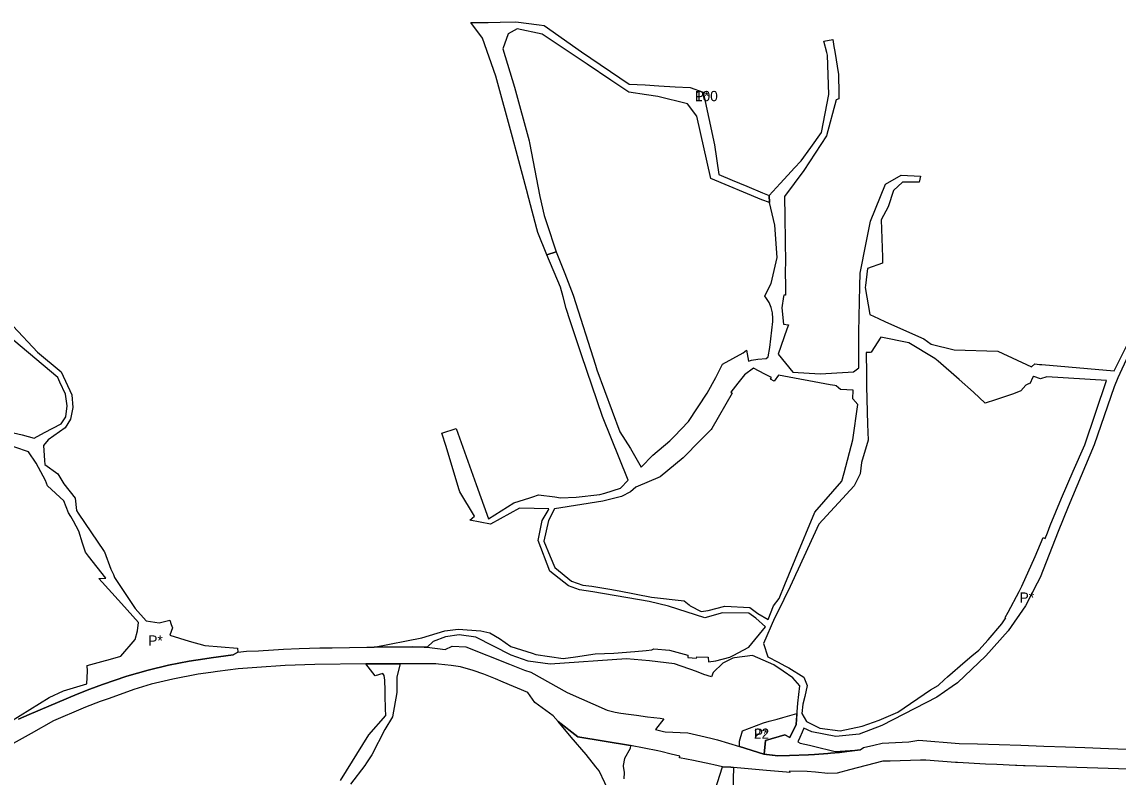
# Model space of a CAD drawing. Extents: x -501732 to -497665, y -1142022 to -1138283.
# Drawn here: x -498822 to -498074, y -1140337 to -1139823 of the extents above; entities that cross this region are included whole.
import ezdxf

# ---------------------------------------------------------------- set-up
doc = ezdxf.new("R2010")
doc.units = 0
for name, color, linetype in [('4', 7, 'Continuous'), ('43', 7, 'Continuous'), ('44', 7, 'Continuous'), ('61', 7, 'Continuous')]:
    doc.layers.add(name, color=color, linetype=linetype)

msp = doc.modelspace()

# ---------------------------------------------------------------- linework, layer by layer
at = {"layer": '4'}
for points in [[(-498823.821, -1140297.619), (-498816.65, -1140294.45), (-498783.82, -1140280.61), (-498775.13, -1140277.11), (-498766.57, -1140274.02), (-498749.99, -1140268.32), (-498735.38, -1140264.17), (-498721.62, -1140260.84), (-498707.43, -1140258.11), (-498696.917, -1140256.467), (-498692.52, -1140255.78), (-498677.54, -1140253.8), (-498674.42, -1140251.94), (-498668.5, -1140251.32), (-498660.19, -1140250.97), (-498656.98, -1140250.84), (-498653.516, -1140250.617), (-498643.16, -1140249.95), (-498632.42, -1140249.56), (-498618.48, -1140249.06), (-498610.11, -1140248.97), (-498586.32, -1140248.64), (-498581.41, -1140248.56), (-498555.48, -1140248.23), (-498547.23, -1140248.6), (-498545.22, -1140248.67), (-498533.03, -1140250.13), (-498528.28, -1140247.99), (-498518.98, -1140248.4), (-498489.252, -1140260.061), (-498478.83, -1140264.15), (-498474.55, -1140265.61), (-498449.81, -1140279.55), (-498422.46, -1140291.59), (-498417.02, -1140292.85), (-498413.36, -1140293.41), (-498407.93, -1140294.24), (-498402.54, -1140294.98), (-498395.12, -1140296.01), (-498386.45, -1140297.04), (-498383.84, -1140297.37), (-498389.51, -1140304.68), (-498384.14, -1140306), (-498382.92, -1140306.3), (-498367.49, -1140306.95), (-498358.69, -1140308.93), (-498351.926, -1140310.544), (-498347.46, -1140311.61), (-498332.46, -1140316.29), (-498315.69, -1140321.52), (-498306.23, -1140322.62), (-498298.17, -1140322.38), (-498285.32, -1140322.01), (-498281.18, -1140321.68), (-498272.152, -1140320.952), (-498270.39, -1140320.81), (-498264.24, -1140320.32), (-498259.25, -1140319.74), (-498250.06, -1140318.42), (-498247.78, -1140316.98), (-498240.77, -1140315.36), (-498235.15, -1140314.06), (-498217.04, -1140313), (-498210.03, -1140312.01), (-498182.55, -1140314.14), (-498170.07, -1140314.45), (-498140.47, -1140315.37), (-498124.82, -1140315.96), (-498110.03, -1140316.5), (-498097.04, -1140316.97), (-498080.83, -1140317.66), (-498061.89, -1140318.32)], [(-498067.02, -1140331.73), (-498116.41, -1140330.16), (-498122.63, -1140329.92), (-498137.66, -1140329.36), (-498138.72, -1140329.34), (-498143.34, -1140329.15), (-498144.23, -1140329.16), (-498156.92, -1140328.57), (-498164.72, -1140328.21), (-498183.68, -1140327.23), (-498185.141, -1140327.124), (-498205.41, -1140325.65), (-498209.03, -1140325.65), (-498229.56, -1140326.13), (-498234.59, -1140326.25), (-498257.27, -1140332.11), (-498265.69, -1140334.29), (-498272.19, -1140334.73), (-498280.63, -1140333.62), (-498286.3, -1140333.18), (-498298.2, -1140332.93), (-498298.11, -1140333.99), (-498300.34, -1140333.79), (-498313.9, -1140332.58), (-498336.48, -1140330.57), (-498338.22, -1140330.42), (-498343.94, -1140330.1), (-498349.77, -1140328.7), (-498352.01, -1140328.16), (-498363.71, -1140325.78), (-498373.23, -1140323.93), (-498373.06, -1140322.8), (-498378.87, -1140321.407), (-498385.91, -1140319.72), (-498388.12, -1140319.18), (-498406.57, -1140315.55), (-498442.63, -1140309.69), (-498456.08, -1140299.18), (-498459.41, -1140295.23), (-498471.93, -1140286.24), (-498476.75, -1140279.49), (-498493.47, -1140272.31), (-498498.65, -1140270.21), (-498506.59, -1140267), (-498513.82, -1140264.42), (-498522.53, -1140261.93), (-498528.97, -1140260.98), (-498537.52, -1140260.05), (-498539.34, -1140259.87), (-498563.73, -1140259.82), (-498569.6, -1140259.82), (-498579.22, -1140259.84), (-498587.11, -1140259.99), (-498621.81, -1140260.32), (-498641.97, -1140261.14), (-498661.41, -1140262.33), (-498674.17, -1140263.33), (-498688.25, -1140265.21), (-498692.64, -1140265.8), (-498701.35, -1140267.06), (-498718.64, -1140270.31), (-498733.5, -1140273.81), (-498745.17, -1140277.37), (-498762.153, -1140283.475), (-498768.23, -1140285.66), (-498778.09, -1140289.42), (-498779.71, -1140290.04), (-498799.88, -1140298.7), (-498815.24, -1140307.37), (-498831.5, -1140316.35)]]:
    msp.add_lwpolyline(points, dxfattribs=at)
at = {"layer": '43'}
for points in [[(-498061.7, -1140037.59), (-498074.46, -1140064.99), (-498076.9, -1140071.11), (-498090.56, -1140110.67), (-498108.39, -1140152.98), (-498115.098, -1140169.861), (-498127.49, -1140201.05), (-498129.511, -1140204.996), (-498137.41, -1140220.42), (-498149.3, -1140237.45), (-498164.48, -1140254.47), (-498183.78, -1140272.87), (-498187.37, -1140275.36), (-498197.77, -1140282.61), (-498235.28, -1140301.81), (-498250.87, -1140307.86), (-498266.58, -1140309.38), (-498283.1, -1140306.27), (-498288.43, -1140303.7), (-498289.64, -1140306.45), (-498291.29, -1140310.21), (-498292.56, -1140313.09), (-498291.06, -1140313.88), (-498284.66, -1140315.3), (-498275.58, -1140317.5), (-498273.4, -1140318.03), (-498267.08, -1140319.56), (-498250.06, -1140318.42), (-498259.25, -1140319.74), (-498264.24, -1140320.32), (-498270.39, -1140320.81), (-498272.152, -1140320.952), (-498281.18, -1140321.68), (-498285.32, -1140322.01), (-498298.17, -1140322.38), (-498306.23, -1140322.62), (-498315.607, -1140321.53), (-498315.491, -1140321.347), (-498314.594, -1140312.178), (-498301.442, -1140308.177), (-498297.97, -1140310.07), (-498296.847, -1140307.688), (-498294.94, -1140303.65), (-498293.75, -1140301.13), (-498292.7, -1140286.76), (-498291.25, -1140274.91), (-498296.02, -1140269.52), (-498302.59, -1140265.01), (-498309.07, -1140260.58), (-498323.5, -1140254.23), (-498335.704, -1140255.871), (-498336.89, -1140256.03), (-498343.63, -1140259.45), (-498350.3, -1140265.88), (-498351.49, -1140268.8), (-498356.78, -1140267.13), (-498361.68, -1140265.12), (-498376.71, -1140259.93), (-498393.76, -1140257.98), (-498409.49, -1140256.52), (-498461.5, -1140260.09), (-498476.48, -1140258.14), (-498488.09, -1140253.97), (-498512.04, -1140241.67), (-498523.57, -1140240.06), (-498532.76, -1140241.54), (-498541.15, -1140244.61), (-498545.22, -1140248.67), (-498547.23, -1140248.6), (-498555.48, -1140248.23), (-498581.41, -1140248.56), (-498548.92, -1140242.09), (-498533.15, -1140237.41), (-498524.03, -1140236.23), (-498508.76, -1140237.36), (-498502.5, -1140238.77), (-498496.04, -1140242.6), (-498488.21, -1140248.03), (-498473.63, -1140252.73), (-498471.13, -1140253.54), (-498452.47, -1140256.2), (-498444.26, -1140255.2), (-498430.79, -1140253.04), (-498418.03, -1140252.63), (-498403.7, -1140251.43), (-498395.92, -1140250.75), (-498392.08, -1140250.42), (-498390.87, -1140249.7), (-498380.09, -1140250.61), (-498367.51, -1140253.98), (-498367.62, -1140255.67), (-498361.58, -1140256.05), (-498361.52, -1140255.12), (-498353.82, -1140255.42), (-498353.58, -1140258.58), (-498348.41, -1140257.97), (-498338.9, -1140255.42), (-498336.718, -1140254.246), (-498325.98, -1140248.47), (-498314.71, -1140234.62), (-498321.12, -1140228.78), (-498326.08, -1140225.5), (-498343.96, -1140225.17), (-498356.086, -1140228.474), (-498380.78, -1140220.65), (-498393.84, -1140217.41), (-498432.34, -1140210.8), (-498441.49, -1140209.43), (-498449.01, -1140206.85), (-498461.59, -1140196.84), (-498469.59, -1140175.97), (-498466.93, -1140162.26), (-498462.85, -1140155.45), (-498462.372, -1140154.316), (-498482.3, -1140153.95), (-498502.12, -1140164.77), (-498516.23, -1140162.11), (-498513.07, -1140159.27), (-498523.05, -1140142.79), (-498523.662, -1140140.759), (-498532.36, -1140111.9), (-498535.385, -1140102.658), (-498525.46, -1140099.67), (-498511.813, -1140137.832), (-498503.51, -1140161.05), (-498486.14, -1140150.27), (-498475.38, -1140146.76), (-498473.2, -1140146.05), (-498469.37, -1140144.8), (-498458.25, -1140146.09), (-498454.39, -1140146.74), (-498443.79, -1140146.41), (-498427.49, -1140144.66), (-498424.15, -1140143.6), (-498413.47, -1140140.15), (-498408.36, -1140134.77), (-498425.83, -1140091.5), (-498440.06, -1140049.48), (-498447.8, -1140026.22), (-498450.51, -1140017.8), (-498452.658, -1140009.919), (-498454.43, -1140003.42), (-498463.633, -1139981.263), (-498457.33, -1139979.14), (-498451.44, -1139994.1), (-498445.81, -1140008.75), (-498430.63, -1140056.46), (-498429.55, -1140059.73), (-498414.01, -1140101.85), (-498406.6, -1140113.23), (-498399.47, -1140125.86), (-498391.35, -1140117.72), (-498379.94, -1140107.93), (-498376.98, -1140104.93), (-498367.04, -1140094.89), (-498354.41, -1140075.56), (-498348.44, -1140064.85), (-498343.92, -1140055.76), (-498329.9, -1140048.05), (-498327.63, -1140046.16), (-498326.21, -1140053.73), (-498324.14, -1140053.08), (-498319.865, -1140052.462), (-498314.21, -1140051.96), (-498312.82, -1140050.68), (-498311.73, -1140044.52), (-498309.61, -1140026.78), (-498309.55, -1140024.6), (-498309.95, -1140020.8), (-498310.85, -1140017.19), (-498312.14, -1140013.66), (-498314.33, -1140010.4), (-498315.09, -1140009.49), (-498314.561, -1140008.389), (-498310.87, -1140000.71), (-498306.6, -1139983.05), (-498308.38, -1139960.97), (-498312.02, -1139945.53), (-498312.25, -1139940.81), (-498304.74, -1139932.72), (-498296.9, -1139924.27), (-498295.019, -1139922.247), (-498290.42, -1139917.3), (-498283.8, -1139908.18), (-498276.41, -1139898), (-498271.57, -1139872.1), (-498272.28, -1139845.36), (-498272.76, -1139843.53), (-498274.81, -1139835.71), (-498268.747, -1139834.697), (-498267.99, -1139839.29), (-498267.45, -1139842.69), (-498264.86, -1139858.44), (-498264.7, -1139871.4), (-498264.68, -1139875), (-498266.38, -1139875.75), (-498273.16, -1139900.19), (-498288.6, -1139923.77), (-498301.64, -1139941.55), (-498301.42, -1139955.34), (-498301.23, -1139971.84), (-498301.06, -1139986.7), (-498301.24, -1139991.74), (-498301.17, -1139995.25), (-498301.03, -1140000.2), (-498300.93, -1140007.983), (-498300.92, -1140008.75), (-498302.19, -1140008.78), (-498302.348, -1140009.778), (-498303.54, -1140017.31), (-498302.35, -1140028.57), (-498299.07, -1140028.89), (-498300.13, -1140032.02), (-498305.9, -1140049.01), (-498295.98, -1140061.11), (-498277.4, -1140062.39), (-498258.207, -1140061.144), (-498254.75, -1140060.92), (-498251.1, -1140058.34), (-498251.1, -1140034.03), (-498250.281, -1140002.595), (-498250.05, -1139993.72), (-498245.93, -1139973.13), (-498243, -1139958.38), (-498232.94, -1139933.15), (-498222.1, -1139927.02), (-498208.976, -1139927.588), (-498209.97, -1139931.8), (-498221.15, -1139931.74), (-498227.48, -1139937.56), (-498230.99, -1139948.51), (-498235.68, -1139957.35), (-498234.9, -1139982.88), (-498234.8, -1139986.89), (-498245.04, -1139990.65), (-498246.528, -1140002.195), (-498246.71, -1140003.61), (-498243.41, -1140021.97), (-498237.54, -1140024.75), (-498232.76, -1140027.01), (-498206.6, -1140038.42), (-498201.77, -1140042.24), (-498186.06, -1140046.03), (-498156.37, -1140046.94), (-498133.22, -1140057.57), (-498131.04, -1140055.59), (-498127.83, -1140055.88), (-498126.38, -1140056.01), (-498076.93, -1140060.36), (-498067.12, -1140040.83)], [(-498827.53, -1140029.8), (-498810.94, -1140047.51), (-498794.68, -1140061.09), (-498787.4, -1140076.72), (-498786.81, -1140085.38), (-498788.4, -1140093.31), (-498791.97, -1140099.03), (-498803.72, -1140107.33), (-498806.72, -1140111.26), (-498806.12, -1140121.34), (-498805.96, -1140124.04), (-498797.06, -1140130.39), (-498792.94, -1140137.4), (-498785.13, -1140146.99), (-498784.33, -1140155.47), (-498783.09, -1140157.29), (-498765.341, -1140183.345), (-498765.14, -1140183.64), (-498760.93, -1140195.45), (-498759.13, -1140198.99), (-498758.32, -1140201.06), (-498744.33, -1140222.22), (-498736.74, -1140230.62), (-498728.02, -1140231.9), (-498720.61, -1140230.13), (-498719.68, -1140233.04), (-498718.91, -1140235.42), (-498720.75, -1140240.46), (-498707.55, -1140244.38), (-498696.93, -1140247.39), (-498674.61, -1140249.31), (-498674.42, -1140251.94), (-498677.54, -1140253.8), (-498692.52, -1140255.78), (-498696.917, -1140256.467), (-498707.43, -1140258.11), (-498721.62, -1140260.84), (-498735.38, -1140264.17), (-498749.99, -1140268.32), (-498766.57, -1140274.02), (-498775.13, -1140277.11), (-498783.82, -1140280.61), (-498816.65, -1140294.45), (-498823.821, -1140297.619)], [(-498830.17, -1140101.82), (-498821.4, -1140104), (-498813.28, -1140106.07), (-498806.03, -1140102.32), (-498794.69, -1140096.4), (-498791.67, -1140091.74), (-498790.59, -1140084.24), (-498791.81, -1140076.15), (-498795.59, -1140067.95), (-498797.14, -1140064.74), (-498827.06, -1140039.73)], [(-498829.21, -1140299.26), (-498803.03, -1140282.74), (-498793.26, -1140278.25), (-498777.38, -1140273.51), (-498776.85, -1140264.93), (-498777.08, -1140261.08), (-498767.03, -1140258.26), (-498761.23, -1140256.7), (-498753.99, -1140254.6), (-498744.4, -1140243.24), (-498742.7, -1140237.5), (-498742.1, -1140231.69), (-498753.68, -1140218.75), (-498769.17, -1140201.83), (-498764.41, -1140201.57), (-498776.207, -1140186.494), (-498778.26, -1140183.87), (-498780.168, -1140177.757), (-498782.76, -1140169.45), (-498786.46, -1140162.69), (-498788.14, -1140159.61), (-498789.78, -1140157.06), (-498793.05, -1140148.95), (-498804.13, -1140138.54), (-498805.36, -1140135.08), (-498811.79, -1140123.29), (-498816.96, -1140115.59), (-498835.67, -1140109.02)], [(-498604.38, -1140339.37), (-498585.04, -1140308.39), (-498573.54, -1140295.16), (-498573.63, -1140290.61), (-498573.83, -1140281.41), (-498573.926, -1140277.036), (-498574.03, -1140272.26), (-498574.2, -1140270.99), (-498574.64, -1140267.8), (-498575.38, -1140266.51), (-498580.72, -1140267.98), (-498587.11, -1140259.99), (-498579.22, -1140259.84), (-498569.6, -1140259.82), (-498563.73, -1140259.82), (-498565.96, -1140268.7), (-498565.894, -1140279.424), (-498568.811, -1140295.953), (-498574.07, -1140304.58), (-498582.98, -1140321.99), (-498586.54, -1140327.36), (-498587.81, -1140329.06), (-498597.43, -1140341.87)], [(-498420.41, -1140349.26), (-498428.12, -1140332.76), (-498430.19, -1140330.18), (-498436.98, -1140321.7), (-498447.13, -1140309.8), (-498448.03, -1140308.73), (-498452.83, -1140303.04), (-498456.08, -1140299.18), (-498442.63, -1140309.69), (-498406.57, -1140315.55), (-498406.88, -1140317.48), (-498410.76, -1140324.38), (-498411.65, -1140329.22), (-498411.59, -1140329.65), (-498410.95, -1140334.03), (-498411.23, -1140338.15)], [(-498350.67, -1140351.45), (-498343.94, -1140330.1), (-498338.22, -1140330.42), (-498336.48, -1140330.57), (-498337.19, -1140354.3)]]:
    msp.add_lwpolyline(points, dxfattribs=at)
for points in [[(-498245.813, -1140062.69), (-498245.72, -1140069), (-498245.695, -1140070.649), (-498245.56, -1140079.69), (-498245.01, -1140096.73), (-498244.66, -1140107.6), (-498249.22, -1140122.8), (-498250.18, -1140130.39), (-498253.29, -1140136.79), (-498254.17, -1140138.59), (-498278.21, -1140164.82), (-498292.45, -1140195.38), (-498294.19, -1140199.34), (-498295.14, -1140201.33), (-498297.91, -1140207.14), (-498306.37, -1140224.92), (-498308.39, -1140228.91), (-498315.93, -1140246.15), (-498313, -1140255.19), (-498306.02, -1140258.81), (-498301.39, -1140261.22), (-498298.65, -1140262.64), (-498288.552, -1140268.889), (-498286.22, -1140274.76), (-498287.91, -1140282.14), (-498289.28, -1140287.42), (-498289.8, -1140293.86), (-498286.8, -1140299.31), (-498277.5, -1140303.8), (-498263.78, -1140305.62), (-498248.72, -1140302.38), (-498237.09, -1140298.36), (-498224.54, -1140292.78), (-498202.1, -1140277.73), (-498196.9, -1140274.61), (-498192.56, -1140270.63), (-498190.56, -1140268.87), (-498178.51, -1140258.27), (-498174.04, -1140254.5), (-498169.27, -1140250.49), (-498162.87, -1140243.45), (-498153.62, -1140232.76), (-498150.82, -1140228.58), (-498151.17, -1140228.44), (-498149.24, -1140224.81), (-498141.66, -1140210.54), (-498140, -1140206.89), (-498130.83, -1140186.73), (-498125.43, -1140173.84), (-498124.04, -1140174.42), (-498122.51, -1140170.7), (-498120.485, -1140165.769), (-498112.8, -1140147.05), (-498104.9, -1140128.69), (-498096.88, -1140110.66), (-498082.17, -1140066.94), (-498122.79, -1140064.35), (-498127.17, -1140065.71), (-498131.65, -1140064.06), (-498132.33, -1140064.71), (-498134.37, -1140069.22), (-498134.83, -1140069.03), (-498137.2, -1140070.01), (-498140.47, -1140073.95), (-498145.53, -1140075.99), (-498157.95, -1140080.06), (-498164.8, -1140082.31), (-498172.81, -1140074.74), (-498182.72, -1140066.17), (-498197.01, -1140053.8), (-498199.22, -1140051.89), (-498217.04, -1140041.19), (-498235.96, -1140037.35), (-498242.66, -1140047.68), (-498243.31, -1140047.71), (-498246.03, -1140047.86)], [(-498370.82, -1140119.62), (-498386.48, -1140132.43), (-498403.14, -1140139.56), (-498406.6, -1140142.83), (-498412.76, -1140145.86), (-498425.44, -1140149.16), (-498458.36, -1140154.39), (-498462.65, -1140162.35), (-498465.69, -1140176.33), (-498461.4, -1140186.69), (-498458.23, -1140194.36), (-498446.94, -1140203.64), (-498439.06, -1140206.23), (-498433.02, -1140206.9), (-498420.67, -1140209.11), (-498414.42, -1140210.23), (-498392.34, -1140214.39), (-498370.01, -1140216.96), (-498366.666, -1140219.765), (-498366.04, -1140220.29), (-498358.48, -1140224.17), (-498353.64, -1140223.54), (-498342.31, -1140220.68), (-498325.42, -1140221.54), (-498319.92, -1140225.51), (-498312.75, -1140229.64), (-498309.12, -1140220.4), (-498305.28, -1140215.33), (-498301.36, -1140205.83), (-498294.38, -1140188.9), (-498281.07, -1140156.62), (-498262.53, -1140135.39), (-498261.081, -1140129.835), (-498255.2, -1140107.29), (-498251.7, -1140083.22), (-498255.09, -1140079.42), (-498254.77, -1140073.58), (-498263.6, -1140073.1), (-498264.88, -1140071.91), (-498266.48, -1140070.42), (-498267.31, -1140070.3), (-498270.56, -1140069.78), (-498305.74, -1140063.26), (-498308.63, -1140067.26), (-498311.13, -1140065.93), (-498310.61, -1140064.89), (-498315.04, -1140062.61), (-498322.89, -1140058.57), (-498329.04, -1140062.94), (-498333.43, -1140068.6), (-498338.3, -1140074.88), (-498337.34, -1140075.59), (-498351.314, -1140099.493), (-498351.71, -1140100.17), (-498358.95, -1140107.54)]]:
    msp.add_lwpolyline(points, close=True, dxfattribs=at)
at = {"layer": '44'}
for points in [[(-498465.57, -1139825.05), (-498440.12, -1139843.07), (-498407.57, -1139864.95), (-498396.76, -1139865.58), (-498387.46, -1139866.13), (-498376.13, -1139866.79), (-498366.03, -1139867.38), (-498357.08, -1139870.37), (-498349.49, -1139906.31), (-498346.55, -1139926.58), (-498337.43, -1139930.36), (-498327.27, -1139934.57), (-498316.68, -1139938.97), (-498312.25, -1139940.81), (-498312.02, -1139945.53), (-498317.03, -1139943.71), (-498351.84, -1139929.26), (-498361.41, -1139886.77), (-498367.74, -1139878.37), (-498387.92, -1139873.33), (-498395.68, -1139872.23), (-498407.82, -1139870.52), (-498420.17, -1139862.22), (-498436.13, -1139851.5), (-498466.78, -1139830.91), (-498483.91, -1139827.39), (-498490.11, -1139830.78), (-498493.62, -1139840.95), (-498485.75, -1139867.1), (-498475.72, -1139903.67), (-498475.454, -1139905.076), (-498468.54, -1139941.63), (-498465.55, -1139954.43), (-498463.929, -1139959.303), (-498457.33, -1139979.14), (-498463.633, -1139981.263), (-498469.91, -1139966.15), (-498470.57, -1139963.59), (-498475.92, -1139942.9), (-498477.58, -1139936.75), (-498483.736, -1139913.929), (-498487.19, -1139901.13), (-498498.38, -1139859.65), (-498507.55, -1139833.78), (-498515.401, -1139823.08), (-498503.66, -1139822.92), (-498495.48, -1139822.79), (-498484.9, -1139822.62), (-498469.03, -1139824.62)], [(-498296.847, -1140307.688), (-498297.97, -1140310.07), (-498301.442, -1140308.177), (-498314.594, -1140312.178), (-498315.491, -1140321.347), (-498315.607, -1140321.53), (-498315.69, -1140321.52), (-498332.46, -1140316.29), (-498332.38, -1140312.65), (-498330.393, -1140305.539), (-498316.108, -1140300.184), (-498312.163, -1140299.065), (-498306.733, -1140297.525), (-498302.78, -1140296.403), (-498293.206, -1140293.688), (-498293.75, -1140301.13), (-498294.94, -1140303.65)]]:
    msp.add_lwpolyline(points, close=True, dxfattribs=at)

# ---------------------------------------------------------------- texts
at = {"layer": '43'}
for rotation, p in [(359.497419, (-498141.448, -1140218.257)), (359.497417, (-498735.437, -1140247.499))]:
    msp.add_text('P*', height=7, rotation=rotation, dxfattribs=at).set_placement(p)
at = {"layer": '44'}
msp.add_text('P*', height=7, dxfattribs=at).set_placement((-498362.798, -1139876.632))
msp.add_text('P*', height=7, rotation=359.497419, dxfattribs=at).set_placement((-498322.579, -1140310.987))
at = {"layer": '61'}
for s, p in [('100', (-498362.77, -1139876.632)), ('22', (-498322.579, -1140310.986))]:
    msp.add_text(s, height=7, dxfattribs=at).set_placement(p)

doc.saveas('drawing.dxf')
